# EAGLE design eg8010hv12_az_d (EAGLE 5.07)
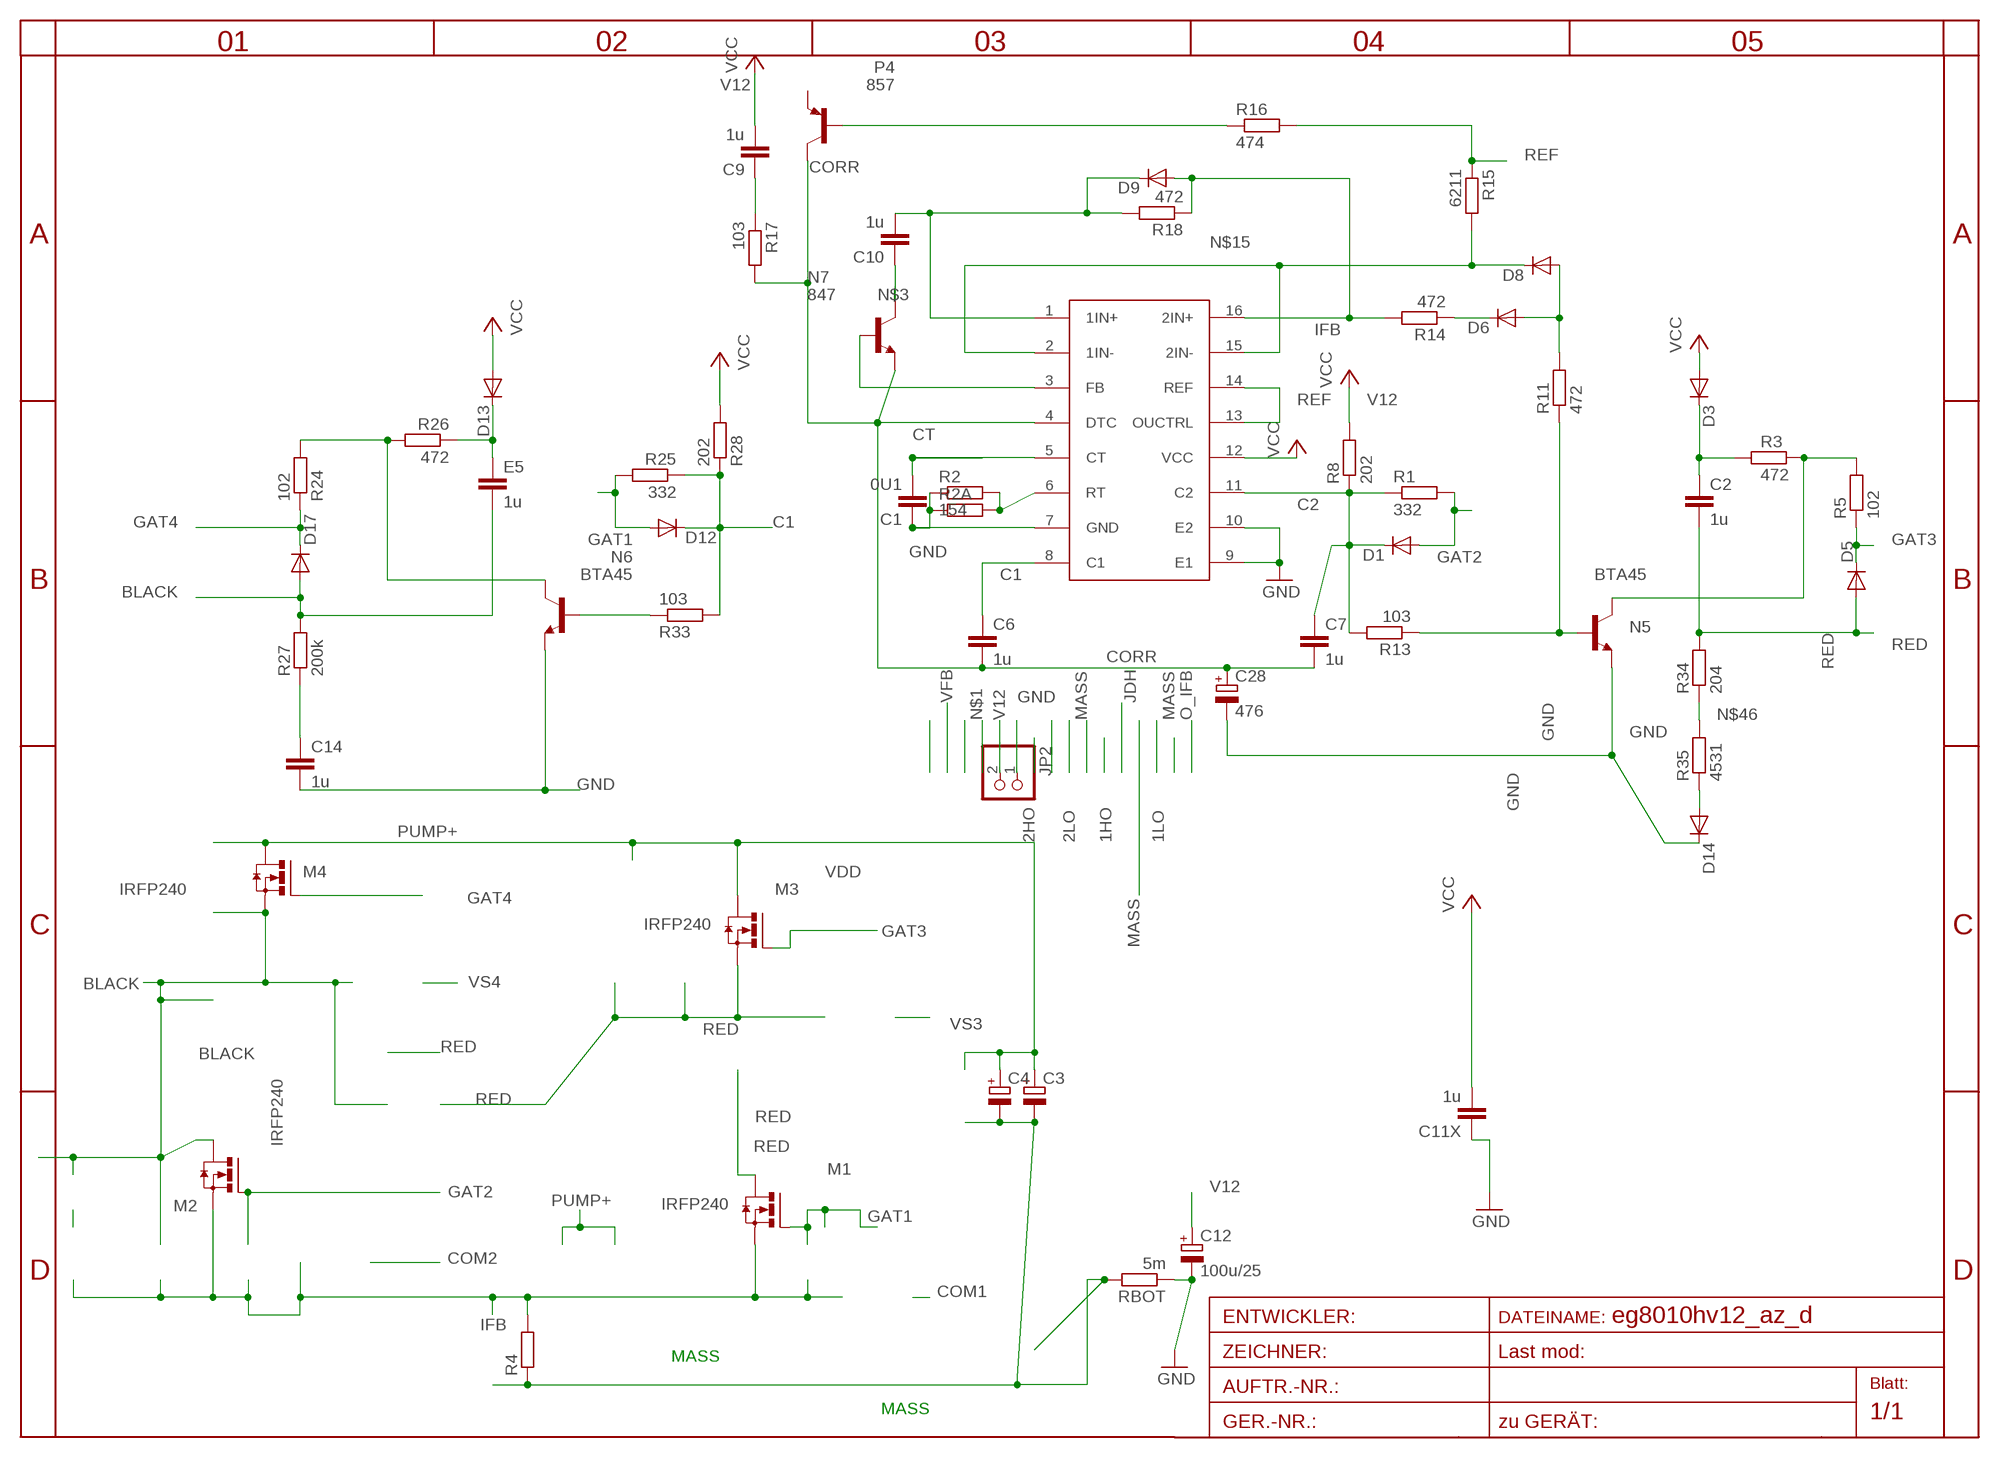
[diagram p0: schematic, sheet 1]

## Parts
7500  AZ7500SO16  [SO16]
C1  0U1  C-EUC0805  [C0805]
C2  1u  C-EUC1206  [C1206]
C3  CPOL-EUE5-13  [E5-13]
C4  CPOL-EUE5-13  [E5-13]
C6  1u  C-EUC0805  [C0805]
C7  1u  C-EUC0805  [C0805]
C9  1u  C-EUC0805  [C0805]
C10  1u  C-EUC1206  [C1206]
C11X  1u  C-EUC1206  [C1206]
C12  100u/25  CPOL-EUD  [PANASONIC_D]
C14  1u  C-EUC1206  [C1206]
C28  476  CPOL-EUA  [PANASONIC_A]
D1  DIODE-MINIMELF  [MINIMELF]
D3  DIODE-SMA-DO214  [SMA-DO214AC]
D5  DIODE-MINIMELF  [MINIMELF]
D6  DIODE-MINIMELF  [MINIMELF]
D8  DIODE-MINIMELF  [MINIMELF]
D9  DIODE-MINIMELF  [MINIMELF]
D12  DIODE-MINIMELF  [MINIMELF]
D13  DIODE-SMA-DO214  [SMA-DO214AC]
D14  DIODE-MINIMELF  [MINIMELF]
D17  DIODE-MINIMELF  [MINIMELF]
E5  1u  C-EUC1206  [C1206]
JP2  PINHD-1X2STR  [1X02]
M1  IRFP240  [TO247BV]
M2  IRFP240  [TO247BV]
M3  IRFP240  [TO247BV]
M4  IRFP240  [TO247BV]
N5  BTA45  SMBTA45HV  [SOT23HV]
N6  BTA45  SMBTA45HV  [SOT23HV]
N7  847  BC847ALT1SMD  [SOT23]
P4  857  BC857ALT1SMD  [SOT23-BEC]
R1  332  R-EU_R0805  [R0805]
R2  154  R-EU_R0805  [R0805]
R2A  R-EU_R0805  [R0805]
R3  472  R-EU_R0805  [R0805]
R4  R-EU_0309/10  [0309/10]
R5  102  R-EU_R1206  [R1206]
R8  202  R-EU_R0805  [R0805]
R11  472  R-EU_R0805  [R0805]
R13  103  R-EU_R0805  [R0805]
R14  472  R-EU_R0805  [R0805]
R15  6211  R-EU_R1206  [R1206]
R16  474  R-EU_R1206  [R1206]
R17  103  R-EU_R1206  [R1206]
R18  472  R-EU_R0805  [R0805]
R24  102  R-EU_R1206  [R1206]
R25  332  R-EU_R0805  [R0805]
R26  472  R-EU_R0805  [R0805]
R27  200k  R-EU_R1206  [R1206]
R28  202  R-EU_R0805  [R0805]
R33  103  R-EU_R0805  [R0805]
R34  204  R-EU_R0805  [R0805]
R35  4531  R-EU_R0805  [R0805]
RBOT  5m  R-EU_0204/5  [0204/5]

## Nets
BLACK: D17.A E5.2 M2.D M4.S R27.2
C1: 7500.8(C1) C6.1 D12.C R25.1 R28.1 R33.2
C2: 7500.11(C2) C7.1 D1.C R1.1 R8.1 R13.2
CORR: 7500.4(DTC) C6.2 C7.2 C28.+ N7.2(E) P4.C R17.2
CT: 7500.5(CT) C1.2
GAT1: D12.A M1.G R25.2
GAT2: D1.A M2.G R1.2
GAT3: D5.C M3.G R5.1
GAT4: D17.C M4.G R24.1
GND: 7500.7(GND) 7500.9(E1) 7500.10(E2) C1.1 C11X.1 C12.- C14.2 C28.- D14.C JP2.1 N5.2(E) N6.2(E) R2.1 R2A.1 RBOT.1
IFB: 7500.16(2IN+) D9.A M1.S M2.S R4.2 R14.2 R18.1
MASS: C3.- C4.- R4.1 RBOT.2
N$3: 7500.1(1IN+) C10.2 D9.C R18.2
N$4: C2.1 D3.K(C) R3.1
N$5: N5.3(C) R3.2 R5.2
N$11: N5.1(B) R11.1 R13.1
N$13: D6.A D8.A R11.2
N$15: 7500.2(1IN-) 7500.15(2IN-) D8.C R15.2
N$36: D6.C R14.1
N$37: P4.B R16.1
N$38: 7500.6(RT) R2.2 R2A.2
N$39: C9.1 R17.1
N$40: 7500.3(FB) N7.1(B)
N$41: C10.1 N7.3(C)
N$42: D13.K(C) E5.1 R26.1
N$43: N6.3(C) R24.2 R26.2
N$44: N6.1(B) R33.1
N$45: C14.1 R27.1
N$46: R34.1 R35.2
N$47: D14.A R35.1
PUMP+: C3.+ C4.+ M3.D M4.D
RED: C2.2 D5.A M1.D M3.S R34.2
REF: 7500.13(OUCTRL) 7500.14(REF) R15.1 R16.2
V12: 7500.12(VCC) C9.2 C11X.2 C12.+ D3.A D13.A JP2.2 R8.2 R28.2 ; supply symbol labelled VCC
Unconnected: P4.E

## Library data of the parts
7500 = az7500:AZ7500
C1 C2 C6 C7 C9 C10 C11X C14 E5 = rcl:C-EU: CAPACITOR, European symbol
C3 C4 C12 C28 = rcl:CPOL-EU: POLARIZED CAPACITOR, European symbol
D1 D3 D5 D6 D8 D9 D12-D14 D17 = diode:DIODE-: DIODE
JP2 = pinhead:PINHD-1X2: PIN HEADER
M1-M4 = transistor-power:IRFP240: HEXFET Power MosFet Source: http://www.irf.com/
N5 N6 = transistor-npn:SMBTA45
N7 = transistor-npn:BC847*: NPN Transistor
P4 = transistor-pnp:BC857*: PNP Transistror
R1 R2 R2A R3-R5 R8 R11 R13-R18 R24-R28 R33-R35 RBOT = rcl:R-EU_: RESISTOR, European symbol

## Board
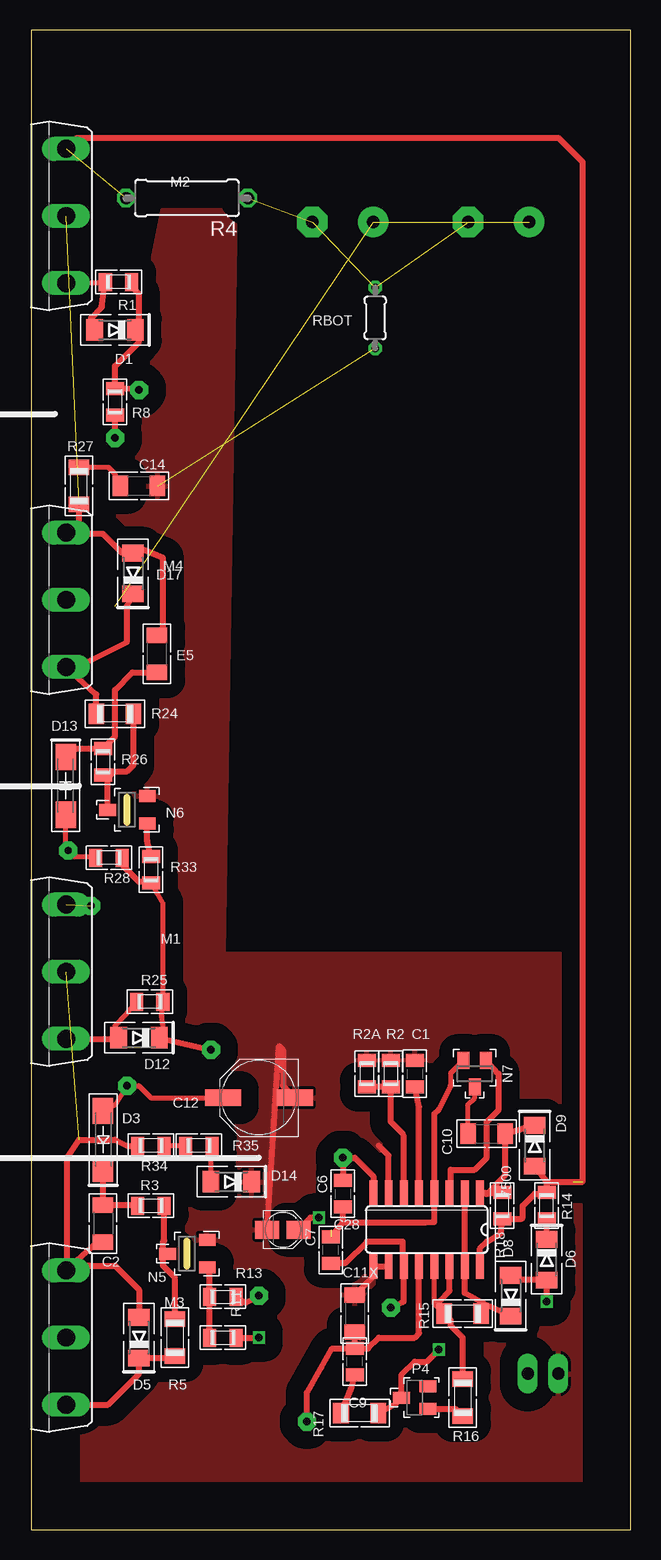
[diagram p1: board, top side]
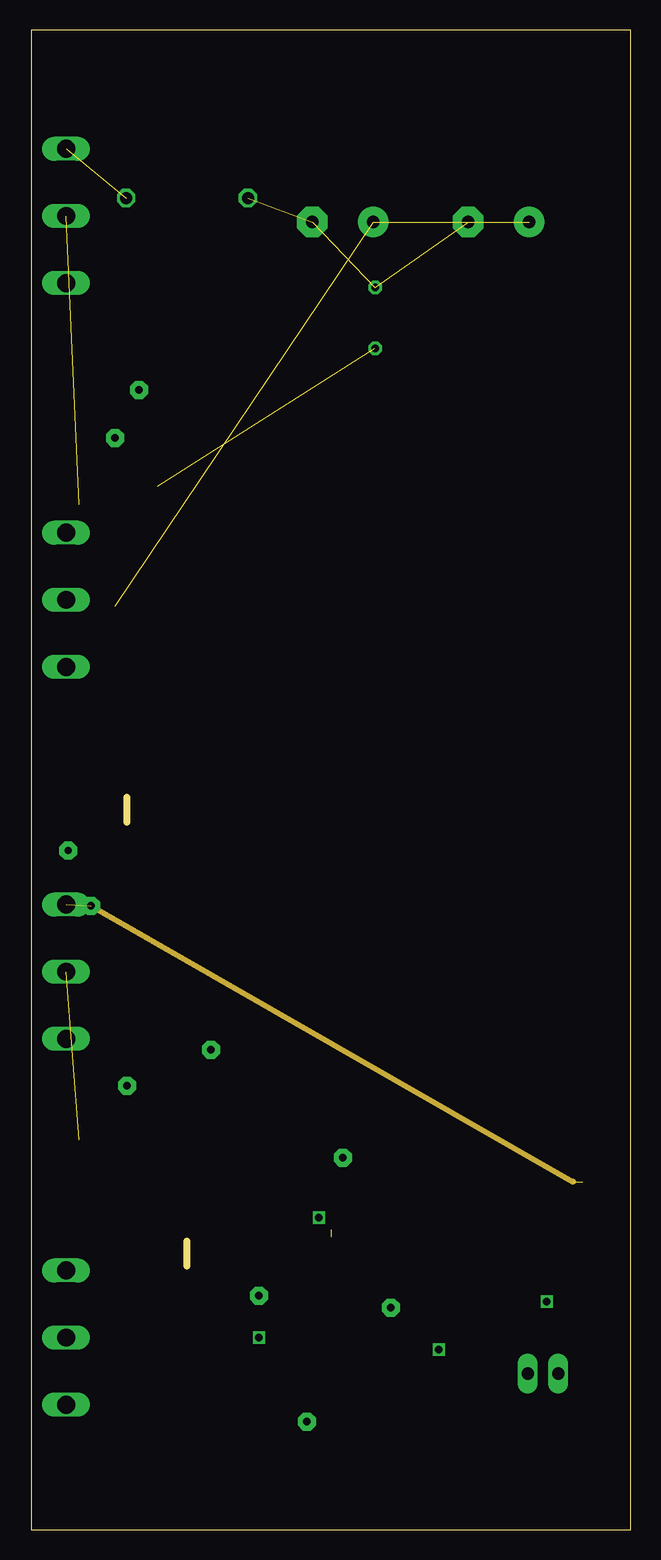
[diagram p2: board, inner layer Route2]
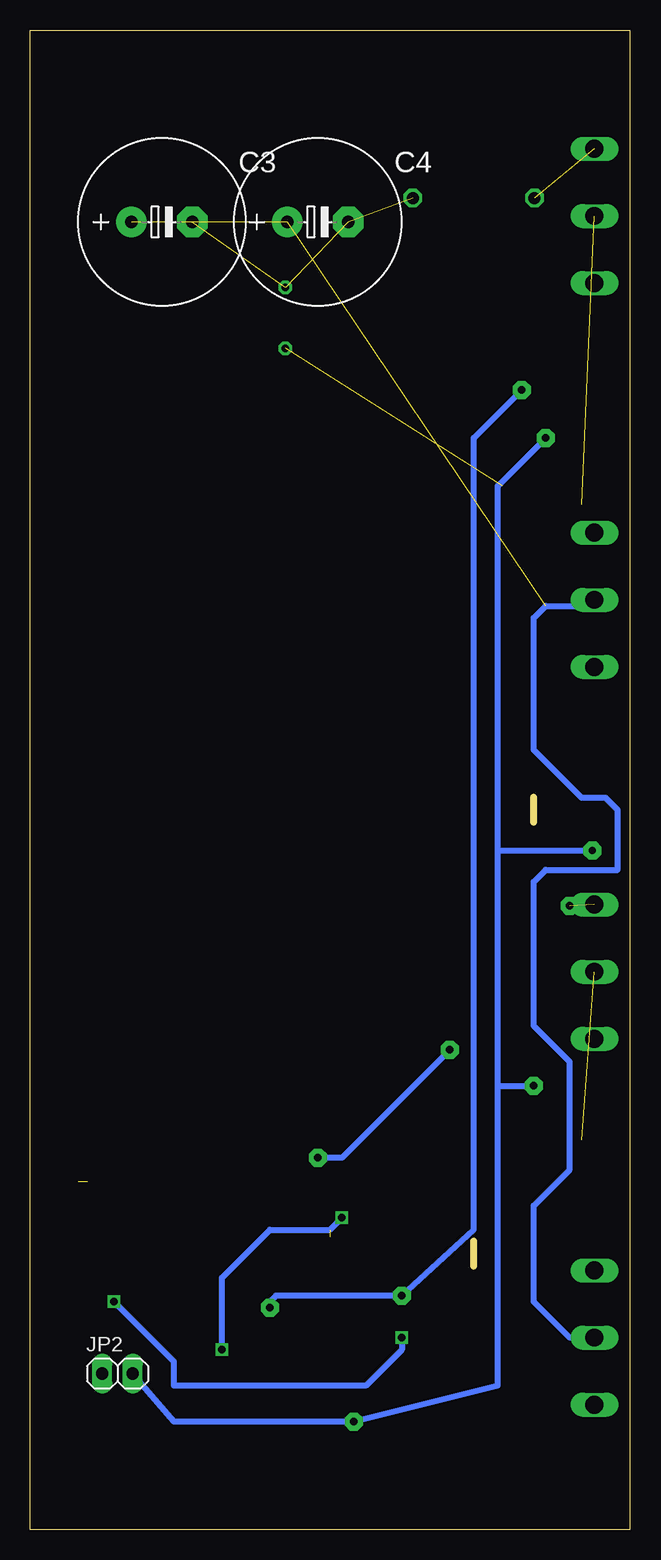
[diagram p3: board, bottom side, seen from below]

Size 50 x 125 mm. Coordinates in mm from the lower left corner, seen from the top.
Outline: 0,0 50,0 50,125 0,125 0,0
Copper layers (1*16): Top 0.035mm / dielectric 1.5mm / Bottom 0.035mm
Design rules "default *": minimum track width 10mil, minimum drill 20mil, track to track 8mil, track to pad 8mil, pad to pad 8mil, via to via 8mil, smd to smd 8mil, copper to edge 4mm, drill to drill 8mil, minimum pad ring 10mil, minimum via ring 8mil, stop-mask expansion 4mil, vias tented up to drill 0mil, thermal gap 10mil

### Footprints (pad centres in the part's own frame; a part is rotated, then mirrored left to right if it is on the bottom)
SO16 = smd 2.032 x 0.66: 1 -3.073,4.445; 2 -3.073,3.175; 3 -3.073,1.905; 4 -3.073,0.635; 5 -3.073,-0.635; 6 -3.073,-1.905; 7 -3.073,-3.175; 8 -3.073,-4.445; 9 3.073,-4.445; 10 3.073,-3.175; 11 3.073,-1.905; 12 3.073,-0.635; 13 3.073,0.635; 14 3.073,1.905; 15 3.073,3.175; 16 3.073,4.445
C0805 = smd 1.1 x 1.5: 1 -1.1,0; 2 1.1,0
C1206 = smd 1.3 x 1.7: 1 -1.55,0; 2 1.55,0
E5-13 = drill 1.016 pad 2.54 round: + -2.54,0 | drill 1.016 pad 2.54 octagon: - 2.54,0
PANASONIC_D = smd 3 x 1.4: + 3,0; - -3,0
PANASONIC_A = smd 2 x 1.5: + 1.3,0; - -1.3,0
MINIMELF = smd 1.4 x 1.8: A 1.7,0; C -1.7,0
SMA-DO214AC = smd 2.2 x 1.7: A 2.4,0; K -2.4,0
1X02 = drill 1.016 pad 1.676 long: 1 -1.27,0; 2 1.27,0
TO247BV = drill 1.499 long: D 0,-2.921; G -5.588,-2.921; S 5.588,-2.921
SOT23HV = smd 1 x 1.4: 1 -1.15,-1.7; 2 1.15,-1.7; 3 0,1.6
SOT23 = smd 1 x 1.4: 1 -0.95,-1.1; 2 0.95,-1.1; 3 0,1.1
SOT23-BEC = smd 1 x 1.4: B -0.95,-1.1; C 0,1.1; E 0.95,-1.1
R0805 = smd 1.1 x 1.5: 1 -1.1,0; 2 1.1,0
0309/10 = drill 1 octagon: 1 -5.08,0; 2 5.08,0
R1206 = smd 1.3 x 1.7: 1 -1.55,0; 2 1.55,0
0204/5 = drill 0.6 octagon: 1 -2.54,0; 2 2.54,0

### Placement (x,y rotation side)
7500  33,25 270 top
C1  32,38 270 top
C2  6,25.5 270 top
C3  39,109 0 bottom
C4  26,109 0 bottom
C6  26,28 270 top
C7  25,23.3 90 top
C9  27,14 90 top
C10  38,33 0 top
C11X  27,18 270 top
C12  19,36 180 top
C14  9,87 0 top
C28  21,25 0 top
D1  7,100 180 top
D3  6,32.5 90 top
D5  9,16 90 top
D6  43,22.5 270 top
D8  40,19.5 90 top
D9  42,32 270 top
D12  9,41 180 top
D13  2.9,62 270 top
D14  16.7,29 180 top
D17  8.5,79.7 90 top
E5  10.5,73 90 top
JP2  42.7,13 0 bottom
M1  0,46.5 90 top
M2  0,109.5 90 top
M3  0,16 90 top
M4  0,77.5 90 top
N5  13,23 90 top
N6  8,60 90 top
N7  37,38 180 top
P4  32,11 90 top
R1  7.3,104 180 top
R2  30,38 270 top
R2A  28,38 270 top
R3  10,27 0 top
R4  13,111 180 top
R5  12,16 90 top
R8  7,94 270 top
R11  16,16 0 top
R13  16,19.4 0 top
R14  43,27 90 top
R15  36,18 0 top
R16  36,11 90 top
R17  27.4,9.7 0 top
R18  39.3,27 90 top
R24  7,68 0 top
R25  9.9,44 180 top
R26  6,64 270 top
R27  4,87 270 top
R28  6.5,56 180 top
R33  10,55 270 top
R34  10,32 180 top
R35  14,32 180 top
RBOT  28.7,101 90 top

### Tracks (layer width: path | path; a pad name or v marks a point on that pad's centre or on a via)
BLACK  (1 unrouted)
  Top 0.5: R27.2 4,83.93 3.54,83.46 | 3.54,83.46 M4.S 3.07,83 | E5.2 10.45,74.5 11,74.5 11,81 9.3,81.7 D17.A 7.6,81.4 6,83 4,83 3.54,83.46
C1  (via drill 0.6 pad 1.5)
  Top 0.406: R33.2 11,52.2 R25.1 10.9,42.8 11,42 11,41.3 D12.C
  Top 0.5: 7500.8 28.56,29.45 27,31 26.1,31 C6.1 v26,31 | D12.C v15,40 | R28.1 7.6,55.4 9,54 9.9,54 R33.2
  Bottom 0.5: v15,40 24,31 v26,31
C2  (via drill 0.6 pad 1.5)
  Top 0.5: R1.1 8.1,103.9 9,103 9,100.3 D1.C 9,99.7 9,99 7,97 R8.1 7.9,95.1 v9,95 | R13.2 17.9,18.9 v19,19.5 | v30,18.5 31,19 31.09,19 7500.11 31,22.02 31,24 28,24 26.2,22.2 C7.1
  Bottom 0.5: v9,95 13,91 13,25 v19,19.5 29.5,19.5 30,19 v30,18.5
CORR  (via drill 0.6)  (1 unrouted)
  Top 0.406: 35,37 35,38.05 N7.2
  Top 0.5: 35,37 34,35 33.64,34.63 7500.4 33.64,25.64 32.9,25.6 26,25.6 | C7.2 26,25.6 | 26,25.6 C6.2 | v34,15 33,14 32,14 30.9,12.9 P4.C 30.35,10.45 R17.2 | v24,26 23.3,26 C28.+
  Bottom 0.5: v34,15 34,21 30,25 25,25 v24,26
CT
  Top 0.5: 7500.5 32.36,35.27 C1.2
GAT1
  Top 0.406: R25.2 7.9,42.9 7,42 7,41.3 D12.A
  Top 0.5: M1.G 7.21,40.91 D12.A
GAT2
  Top 0.406: M2.G 5.9,103.91 R1.2
  Top 0.5: R1.2 5.9,101.9 5,101 5,100.3 D1.A
GAT3
  Top 0.5: M3.G 6.41,10.41 9,13 D5.C 11.85,14.3 R5.1
GAT4
  Top 0.5: D17.C 8,77 8,74 4,72 3.25,72 M4.G 5.45,69.62 R24.1
GND  (1 unrouted)
  Top 0.5: 7500.7 29.83,31.18 29,32 | 7500.10 7500.9 28.56,21.11 C11X.1 | C28.- 20.7,40.3 21,40 21,37 C12.-
  pour Top (isolate 1.5): 4,105 10,105 11,110 17,110 16,48 48,48 48,2 4,2
IFB  (via drill 0.6 pad 1.5)  (3 unrouted)
  Top 0.5: 43,29 D9.A | 7500.16 37.44,23.45 38,24 39.2,24.7 R18.1 40.9,25.9 41,26 41,27 42,28 42.9,28 R14.2 43,29 | 43,29 46,29 46,114 44,116 3.83,116 M2.S
  Route2 0.5: v5,52 45.2,29
MASS  (3 unrouted)
N$3
  Top 0.5: D9.C 41.8,33.7 C10.2 39.55,29.55 38,28 | 7500.1 37.83,28.07 37.95,27.95 38,28 | R18.2 38.9,28.1 38,28
N$4
  Top 0.406: 8.9,27.05 R3.1
  Top 0.5: D3.K C2.1 8.9,27.05
N$5
  Top 0.5: R5.2 12,21 11,22 11,22.6 N5.3 11,23.4 11,24 11.1,24.1 R3.2
N$11
  Top 0.5: 15,21.55 N5.1 14.9,21.65 R13.1 R11.1
N$13  (via drill 0.6)
  Top 0.5: R11.2 v19,16 | v43,19 D6.A 40.4,20.8 D8.A
  Bottom 0.5: v19,16 19,15 22,12 38,12 38,14 v43,19
N$15
  Top 0.5: 7500.2 7500.15 36.17,19.73 37.97,18.73 | 37.97,18.73 D8.C | R15.2 37.55,18.3 37.97,18.73
N$36
  Top 0.5: D6.C R14.1
N$37
  Top 0.5: P4.B 35.4,10.05 R16.1
N$38
  Top 0.5: 7500.6 31.09,32.8 31,33 30,34 R2.2 R2A.2
N$39
  Top 0.5: C9.1 26.75,11.9 R17.1
N$40
  Top 0.5: N7.1 38.95,38 39,38 39,35 38,34 38,31 37,30 35,30 35,28.17 7500.3
N$41
  Top 0.406: C10.1 36.45,35.45 37,36 N7.3
N$42
  Top 0.5: D13.K 3,65 3.1,65.1 R26.1 7,66.1 7,70 8.45,71.45 E5.1
N$43
  Top 0.5: N6.3 6.4,62.5 | 6.4,62.5 R26.2 | R24.2 8.55,63.75 8,63.2 6.9,63.2 6.4,62.5
N$44
  Top 0.5: N6.1 9.7,57.4 R33.1
N$45
  Top 0.406: R27.1 6.45,88.55 7,88 7,87.45 C14.1
N$46
  Top 0.406: R35.2 R34.1
N$47
  Top 0.406: D14.A 15,31.9 R35.1
PUMP+  (2 unrouted)
  Bottom 0.5: M3.D 5,16 8,19 8,27 5,30 5,39 8,42 8,54 7,55 1,55 1,60 2,61 4,61 8,65 8,76 7,77 3.66,77 M4.D
RED  (1 unrouted)
  Top 0.406: M3.S 3.16,22.16 7,22
  Top 0.5: D5.A 9,20 7,22 3.57,22 M3.S 5.52,23.95 C2.2 | R34.2 8,32 7,32.5 4,32.5 3,31 3,22.32 3.16,22.16
REF
  Top 0.406: 7500.13 33.64,18.82 R15.1
  Top 0.5: 7500.14 34.91,19.91 34,19 34,18.45 R15.1 35,17.45 35,17 36,16 R16.2
V12  (via drill 0.6 pad 1.5)
  Top 0.406: C12.+ 10,36 9,37 v8,37 7,35.4 D3.A | 4.9,56.1 3.6,56.1 v3.1,56.6 2.9,56.8 D13.A
  Top 0.5: v7,91 R8.2 | 4.9,56.1 R28.2 | 7500.12 32.36,16.36 32,16 29,16 28.1,15.1 C9.2 | 27.45,16 C11X.2 C9.2 | v23,9 23,11.4 24.2,13.5 25.1,15.1 C9.2
  Bottom 0.5: 11,56.6 11,87 v7,91 | 11,37 v8,37 | 11,37 11,56.6 | 11,56.6 v3.1,56.6 | 11,37 11,12 v23,9 38,9 JP2.2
